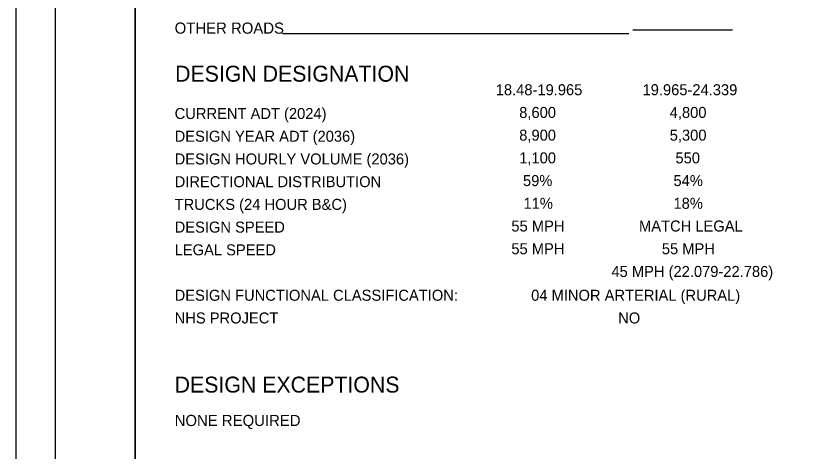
# Model space of a CAD drawing. Extents: x 0 to 34, y 0 to 22.
# Drawn here: x 0 to 9.95, y 5.64 to 11.1 of the extents above; entities that cross this region are included whole.
import ezdxf

# ---------------------------------------------------------------- set-up
doc = ezdxf.new("R2010")
doc.units = 0
for name, color, linetype in [('GM_X_County', 7, 'Continuous'), ('GM_X_Minor_Lake', 7, 'Continuous'), ('GM_X_Minor_Lake_Text', 7, 'Continuous'), ('GM_X_Minor_River_Text', 7, 'Continuous')]:
    doc.layers.add(name, color=color, linetype=linetype)

msp = doc.modelspace()

# ---------------------------------------------------------------- linework, layer by layer
at = {"layer": 'GM_X_County'}
msp.add_lwpolyline([(0, 0), (34, 0), (34, 22), (0, 22)], close=True, dxfattribs=at)
at = {"layer": 'GM_X_Minor_Lake_Text'}
for p, q in [((7.7, 10.8767), (3.3471, 10.8767)), ((9, 10.9223), (7.75, 10.9223))]:
    msp.add_line(p, q, dxfattribs=at)
at = {"layer": 'GM_X_Minor_River_Text'}
for points in [[(0.5, 21.5), (1.5, 21.5), (1.5, 0.5), (0.5, 0.5)], [(1.5, 21.5), (33.5, 21.5), (33.5, 0.5), (1.5, 0.5)]]:
    msp.add_lwpolyline(points, close=True, dxfattribs=at)

# ---------------------------------------------------------------- texts
at = {"layer": 'GM_X_Minor_Lake'}
for s, height, p in [('OTHER ROADS', 0.14, (1.9944, 10.8767)), ('18.48-19.965', 0.138, (6.0269, 10.1047)), ('19.965-24.339', 0.138, (7.8705, 10.1047)), ('CURRENT ADT (2024)', 0.138, (1.9944, 9.8062)), ('8,600', 0.138, (6.3216, 9.8197)), ('4,800', 0.138, (8.2116, 9.8197)), ('DESIGN YEAR ADT (2036)', 0.138, (1.9944, 9.5212)), ('8,900', 0.138, (6.3216, 9.5347)), ('5,300', 0.138, (8.2116, 9.5347)), ('DESIGN HOURLY VOLUME (2036)', 0.138, (1.9944, 9.2362)), ('1,100', 0.138, (6.3216, 9.2497)), ('550', 0.138, (8.2839, 9.2497)), ('DIRECTIONAL DISTRIBUTION', 0.138, (1.9944, 8.9512)), ('59%', 0.138, (6.369, 8.9647)), ('54%', 0.138, (8.259, 8.9647)), ('TRUCKS (24 HOUR B&C)', 0.138, (1.9944, 8.6662)), ('11%', 0.138, (6.3755, 8.6797)), ('18%', 0.138, (8.259, 8.6797)), ('DESIGN SPEED', 0.138, (1.9944, 8.3812)), ('55 MPH', 0.138, (6.223, 8.3947)), ('MATCH LEGAL', 0.138, (7.8263, 8.3947)), ('LEGAL SPEED', 0.138, (1.9944, 8.0962)), ('55 MPH', 0.138, (6.223, 8.1097)), ('55 MPH', 0.138, (8.113, 8.1097)), ('45 MPH (22.079-22.786)', 0.138, (7.4798, 7.8247)), ('DESIGN FUNCTIONAL CLASSIFICATION:', 0.138, (1.9944, 7.5262)), ('04 MINOR ARTERIAL (RURAL)', 0.138, (6.4716, 7.5262)), ('NHS PROJECT', 0.138, (1.9944, 7.2412)), ('NO', 0.138, (7.5647, 7.2412)), ('DESIGN EXCEPTIONS', 0.2, (1.9944, 6.3744)), ('NONE REQUIRED', 0.14, (1.9944, 5.9544))]:
    msp.add_text(s, height=height, dxfattribs=at).set_placement(p)
at = {"layer": 'GM_X_Minor_Lake_Text'}
msp.add_text('DESIGN DESIGNATION', height=0.2, dxfattribs=at).set_placement((2, 10.2747))

doc.saveas('drawing.dxf')
